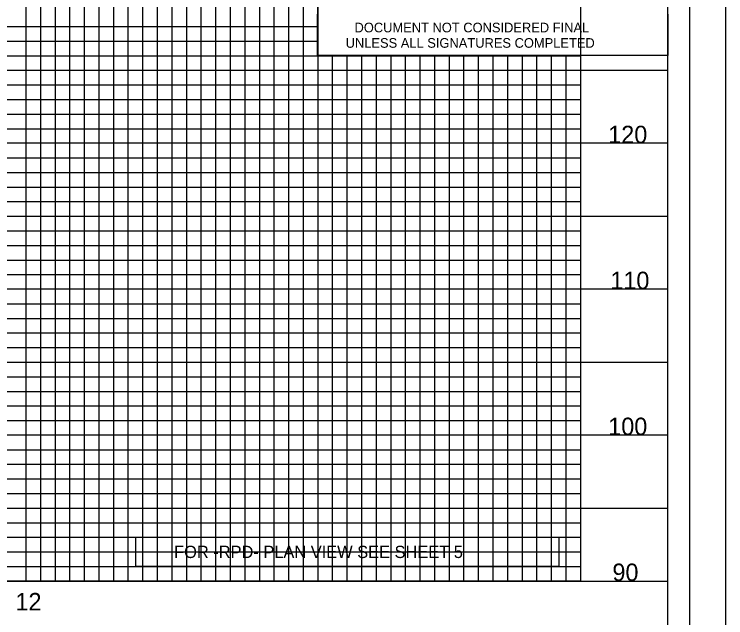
# Model space of a CAD drawing. Extents: x -130 to 890, y -29895 to -29235.
# Drawn here: x 646 to 889.8, y -29562.3 to -29355.5 of the extents above; entities that cross this region are included whole.
import ezdxf

# ---------------------------------------------------------------- set-up
doc = ezdxf.new("R2010")
doc.units = 0
for name, color, linetype in [('Exist Vertical Profile Horizontal Axis Label Major', 7, 'Continuous'), ('Exist Vertical Profile Vertical Axis Label', 7, 'Continuous'), ('Prop Grid Mask', 7, 'Continuous'), ('Prop PFL Text', 7, 'Continuous'), ('Scratch_Level_0', 7, 'Continuous'), ('Sheet Cutting Line CELL', 7, 'Continuous'), ('Sheet Layout Profile Border Port 1', 7, 'Continuous'), ('Sheet Plot Border Inside CELL', 7, 'Continuous'), ('Sheet Plot Border Outside CELL', 7, 'Continuous'), ('Sheet Profile CELL', 7, 'Continuous'), ('Sheet Profile Grid Major CELL', 7, 'Continuous'), ('Sheet Profile Grid Middle CELL', 7, 'Continuous'), ('Sheet Profile Grid Minor CELL', 7, 'Continuous'), ('Sheet Sticker Exception Certification CELL', 7, 'Continuous')]:
    doc.layers.add(name, color=color, linetype=linetype)

msp = doc.modelspace()

# ---------------------------------------------------------------- linework, layer by layer
at = {"layer": 'Exist Vertical Profile Vertical Axis Label'}
msp.add_lwpolyline([(687.65, -29534.75), (832.65, -29534.75), (832.65, -29544.75), (687.65, -29544.75)], close=True, dxfattribs=at)
at = {"layer": 'Prop Grid Mask'}
msp.add_lwpolyline([(687.65, -29534.75), (832.65, -29534.75), (832.65, -29544.75), (687.65, -29544.75)], close=True, dxfattribs=at)
at = {"layer": 'Scratch_Level_0'}
msp.add_lwpolyline([(450, -29249.75), (750, -29249.75), (749.97, -29346.38), (840, -29346.38), (840, -29549.75), (450, -29549.75)], close=True, dxfattribs=at)
at = {"layer": 'Sheet Cutting Line CELL'}
msp.add_line((889.8, -29894.75), (889.8, -29234.75), dxfattribs=at)
at = {"layer": 'Sheet Layout Profile Border Port 1'}
msp.add_lwpolyline([(0, -29249.75), (749.97, -29249.75), (749.97, -29369.63), (840, -29369.75), (840, -29549.75), (0, -29549.75)], close=True, dxfattribs=at)
at = {"layer": 'Sheet Plot Border Inside CELL'}
msp.add_lwpolyline([(-122.4, -29881.28), (877.5, -29881.28), (877.5, -29248.22), (-122.4, -29248.22)], close=True, dxfattribs=at)
at = {"layer": 'Sheet Plot Border Outside CELL'}
msp.add_lwpolyline([(-130.2, -29894.75), (889.8, -29894.75), (889.8, -29234.75), (-130.2, -29234.75)], close=True, dxfattribs=at)
at = {"layer": 'Sheet Profile CELL'}
msp.add_line((-30, -29549.75), (870, -29549.75), dxfattribs=at)
msp.add_lwpolyline([(870, -29249.75), (-30, -29249.75), (-30, -29879.75), (870, -29879.75)], close=True, dxfattribs=at)
at = {"layer": 'Sheet Profile Grid Major CELL'}
for p, q in [((650, -29249.75), (650, -29549.75)), ((675, -29249.75), (675, -29549.75)), ((700, -29249.75), (700, -29549.75)), ((725, -29249.75), (725, -29549.75)), ((750, -29249.75), (750, -29549.75)), ((775, -29369.63), (775, -29549.75)), ((800, -29369.63), (800, -29549.75)), ((825, -29369.63), (825, -29549.75)), ((840, -29369.63), (840, -29549.75)), ((-30, -29374.75), (870, -29374.75)), ((870, -29399.75), (-30, -29399.75)), ((-30, -29424.75), (870, -29424.75)), ((870, -29449.75), (-30, -29449.75)), ((-30, -29474.75), (870, -29474.75)), ((870, -29499.75), (-30, -29499.75)), ((-30, -29524.75), (870, -29524.75))]:
    msp.add_line(p, q, dxfattribs=at)
at = {"layer": 'Sheet Profile Grid Middle CELL'}
for p, q in [((450, -29359.75), (750, -29359.75)), ((450, -29364.75), (750, -29364.75)), ((450, -29369.75), (840, -29369.75)), ((450, -29379.75), (840, -29379.75)), ((450, -29384.75), (840, -29384.75)), ((450, -29389.75), (840, -29389.75)), ((450, -29394.75), (840, -29394.75)), ((450, -29404.75), (840, -29404.75)), ((450, -29409.75), (840, -29409.75)), ((450, -29414.75), (840, -29414.75)), ((450, -29419.75), (840, -29419.75)), ((450, -29429.75), (840, -29429.75)), ((450, -29434.75), (840, -29434.75)), ((450, -29439.75), (840, -29439.75)), ((450, -29444.75), (840, -29444.75)), ((450, -29454.75), (840, -29454.75)), ((450, -29459.75), (840, -29459.75)), ((450, -29464.75), (840, -29464.75)), ((450, -29469.75), (840, -29469.75)), ((450, -29479.75), (840, -29479.75)), ((450, -29484.75), (840, -29484.75)), ((450, -29489.75), (840, -29489.75)), ((450, -29494.75), (840, -29494.75)), ((450, -29504.75), (840, -29504.75)), ((450, -29509.75), (840, -29509.75)), ((450, -29514.75), (840, -29514.75)), ((450, -29519.75), (840, -29519.75)), ((450, -29529.75), (840, -29529.75)), ((450, -29534.75), (840, -29534.75)), ((450, -29539.75), (840, -29539.75)), ((450, -29544.75), (840, -29544.75))]:
    msp.add_line(p, q, dxfattribs=at)
msp.add_lwpolyline([(765, -29384.75), (840, -29384.75)], dxfattribs=at)
at = {"layer": 'Sheet Profile Grid Minor CELL'}
for p, q in [((655, -29249.75), (655, -29549.75)), ((660, -29249.75), (660, -29549.75)), ((665, -29249.75), (665, -29549.75)), ((670, -29249.75), (670, -29549.75)), ((680, -29249.75), (680, -29549.75)), ((685, -29249.75), (685, -29549.75)), ((690, -29249.75), (690, -29549.75)), ((695, -29249.75), (695, -29549.75)), ((705, -29249.75), (705, -29549.75)), ((710, -29249.75), (710, -29549.75)), ((715, -29249.75), (715, -29549.75)), ((720, -29249.75), (720, -29549.75)), ((730, -29249.75), (730, -29549.75)), ((735, -29249.75), (735, -29549.75)), ((740, -29249.75), (740, -29549.75)), ((745, -29249.75), (745, -29549.75)), ((755, -29369.63), (755, -29549.75)), ((760, -29369.63), (760, -29549.75)), ((765, -29369.63), (765, -29549.75)), ((770, -29369.63), (770, -29549.75)), ((780, -29369.63), (780, -29549.75)), ((785, -29369.63), (785, -29549.75)), ((790, -29369.63), (790, -29549.75)), ((795, -29369.63), (795, -29549.75)), ((805, -29369.63), (805, -29549.75)), ((810, -29369.63), (810, -29549.75)), ((815, -29369.63), (815, -29549.75)), ((820, -29369.63), (820, -29549.75)), ((830, -29369.63), (830, -29549.75)), ((835, -29369.63), (835, -29549.75))]:
    msp.add_line(p, q, dxfattribs=at)
at = {"layer": 'Sheet Sticker Exception Certification CELL'}
for p, q in [((749.97, -29369.63), (749.97, -29355.53)), ((869.99, -29355.54), (869.99, -29369.64)), ((869.99, -29369.63), (749.97, -29369.63))]:
    msp.add_line(p, q, dxfattribs=at)

# ---------------------------------------------------------------- texts
at = {"layer": 'Exist Vertical Profile Horizontal Axis Label Major'}
msp.add_text('12', height=6, dxfattribs=at).set_placement((646.44, -29559.81))
at = {"layer": 'Exist Vertical Profile Vertical Axis Label'}
for s, p in [('120', (849.53, -29399.75)), ('110', (850.24, -29449.75)), ('100', (849.53, -29499.75)), ('90', (850.97, -29549.75))]:
    msp.add_text(s, height=6, dxfattribs=at).set_placement(p)
at = {"layer": 'Prop PFL Text'}
msp.add_text('FOR -RPD- PLAN VIEW SEE SHEET 5', height=4.2, dxfattribs=at).set_placement((700.81, -29541.85))
at = {"layer": 'Sheet Sticker Exception Certification CELL'}
for s, p in [('DOCUMENT NOT CONSIDERED FINAL', (762.61, -29361.74)), ('UNLESS ALL SIGNATURES COMPLETED', (759.57, -29367.02))]:
    msp.add_text(s, height=3.3, rotation=0, dxfattribs=at).set_placement(p)

doc.saveas('drawing.dxf')
